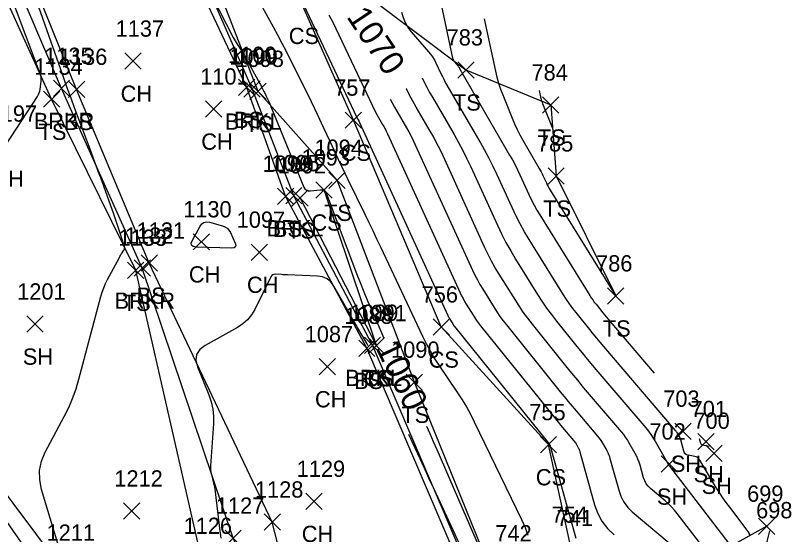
# Model space of a CAD drawing. Extents: x 1592612 to 1596497, y 111838 to 113741.
# Drawn here: x 1592792 to 1592887.3, y 113548.4 to 113612.1 of the extents above; entities that cross this region are included whole.
import ezdxf

# ---------------------------------------------------------------- set-up
doc = ezdxf.new("R2010")
doc.units = 0
for name, color, linetype in [('L_A', 7, 'Continuous'), ('L_I', 7, 'Continuous'), ('L_TIC', 7, 'Continuous'), ('LAWE', 7, 'Continuous'), ('LELB', 7, 'Continuous'), ('LSOGCMA', 7, 'Continuous'), ('LSOGCMA_T', 7, 'Continuous'), ('LSOGCMI', 7, 'Continuous')]:
    doc.layers.add(name, color=color, linetype=linetype)

msp = doc.modelspace()

# ---------------------------------------------------------------- linework, layer by layer
at = {"layer": 'L_TIC'}
for points in [[(1592805.447, 113605.527), (1592807.447, 113607.527)], [(1592807.447, 113605.527), (1592805.447, 113607.527)], [(1592846.35, 113604.446), (1592848.35, 113606.446)], [(1592848.35, 113604.446), (1592846.35, 113606.446)], [(1592796.669, 113602.177), (1592798.669, 113604.177)], [(1592798.669, 113602.177), (1592796.669, 113604.177)], [(1592819.421, 113602.303), (1592821.421, 113604.303)], [(1592821.421, 113602.303), (1592819.421, 113604.303)], [(1592820.08, 113602.103), (1592822.08, 113604.103)], [(1592822.08, 113602.103), (1592820.08, 113604.103)], [(1592798.527, 113602.061), (1592800.527, 113604.061)], [(1592800.527, 113602.061), (1592798.527, 113604.061)], [(1592820.816, 113601.808), (1592822.816, 113603.808)], [(1592822.816, 113601.808), (1592820.816, 113603.808)], [(1592795.452, 113600.853), (1592797.452, 113602.853)], [(1592797.452, 113600.853), (1592795.452, 113602.853)], [(1592815.353, 113599.643), (1592817.353, 113601.643)], [(1592817.353, 113599.643), (1592815.353, 113601.643)], [(1592856.769, 113600.143), (1592858.769, 113602.143)], [(1592858.769, 113600.143), (1592856.769, 113602.143)], [(1592832.529, 113598.277), (1592834.529, 113600.277)], [(1592834.529, 113598.277), (1592832.529, 113600.277)], [(1592830.516, 113590.894), (1592832.516, 113592.894)], [(1592832.516, 113590.894), (1592830.516, 113592.894)], [(1592857.441, 113591.421), (1592859.441, 113593.421)], [(1592859.441, 113591.421), (1592857.441, 113593.421)], [(1592828.931, 113589.704), (1592830.931, 113591.704)], [(1592830.931, 113589.704), (1592828.931, 113591.704)], [(1592824.196, 113588.927), (1592826.196, 113590.927)], [(1592826.196, 113588.927), (1592824.196, 113590.927)], [(1592825.212, 113588.998), (1592827.212, 113590.998)], [(1592827.212, 113588.998), (1592825.212, 113590.998)], [(1592825.981, 113588.728), (1592827.981, 113590.728)], [(1592827.981, 113588.728), (1592825.981, 113590.728)], [(1592813.832, 113583.335), (1592815.832, 113585.335)], [(1592815.832, 113583.335), (1592813.832, 113585.335)], [(1592820.965, 113582.057), (1592822.965, 113584.057)], [(1592822.965, 113582.057), (1592820.965, 113584.057)], [(1592807.456, 113580.722), (1592809.456, 113582.722)], [(1592809.456, 113580.722), (1592807.456, 113582.722)], [(1592805.797, 113579.845), (1592807.797, 113581.845)], [(1592807.797, 113579.845), (1592805.797, 113581.845)], [(1592806.597, 113580.108), (1592808.597, 113582.108)], [(1592808.597, 113580.108), (1592806.597, 113582.108)], [(1592864.761, 113576.691), (1592866.761, 113578.691)], [(1592866.761, 113576.691), (1592864.761, 113578.691)], [(1592793.428, 113573.235), (1592795.428, 113575.235)], [(1592795.428, 113573.235), (1592793.428, 113575.235)], [(1592843.332, 113572.876), (1592845.332, 113574.876)], [(1592845.332, 113572.876), (1592843.332, 113574.876)], [(1592834.177, 113570.255), (1592836.177, 113572.255)], [(1592836.177, 113570.255), (1592834.177, 113572.255)], [(1592834.879, 113570.623), (1592836.879, 113572.623)], [(1592836.879, 113570.623), (1592834.879, 113572.623)], [(1592835.353, 113570.585), (1592837.353, 113572.585)], [(1592837.353, 113570.585), (1592835.353, 113572.585)], [(1592835.353, 113570.585), (1592837.353, 113572.585)], [(1592837.353, 113570.585), (1592835.353, 113572.585)], [(1592829.322, 113568.002), (1592831.322, 113570.002)], [(1592831.322, 113568.002), (1592829.322, 113570.002)], [(1592840.019, 113566.093), (1592842.019, 113568.093)], [(1592842.019, 113566.093), (1592840.019, 113568.093)], [(1592873.035, 113560.076), (1592875.035, 113562.076)], [(1592875.035, 113560.076), (1592873.035, 113562.076)], [(1592856.498, 113558.424), (1592858.498, 113560.424)], [(1592858.498, 113558.424), (1592856.498, 113560.424)], [(1592875.834, 113558.804), (1592877.834, 113560.804)], [(1592877.834, 113558.804), (1592875.834, 113560.804)], [(1592876.826, 113557.367), (1592878.826, 113559.367)], [(1592878.826, 113557.367), (1592876.826, 113559.367)], [(1592871.335, 113556.042), (1592873.335, 113558.042)], [(1592873.335, 113556.042), (1592871.335, 113558.042)], [(1592827.7, 113551.46), (1592829.7, 113553.46)], [(1592829.7, 113551.46), (1592827.7, 113553.46)], [(1592805.288, 113550.276), (1592807.288, 113552.276)], [(1592807.288, 113550.276), (1592805.288, 113552.276)], [(1592822.559, 113548.918), (1592824.559, 113550.918)], [(1592824.559, 113548.918), (1592822.559, 113550.918)], [(1592883.313, 113548.407), (1592885.313, 113550.407)], [(1592885.313, 113548.407), (1592883.313, 113550.407)], [(1592817.761, 113546.936), (1592819.761, 113548.936)], [(1592819.761, 113546.936), (1592817.761, 113548.936)]]:
    msp.add_lwpolyline(points, dxfattribs=at)
at = {"layer": 'LAWE'}
for points in [[(1592886.537, 113460.922), (1592877.744, 113481.574), (1592863.095, 113501.144), (1592852.902, 113518.209), (1592848.805, 113541.382), (1592835.879, 113571.623), (1592826.212, 113589.998), (1592821.08, 113603.103), (1592811.502, 113625.047), (1592801.909, 113656.496), (1592787.746, 113677.481), (1592769.551, 113701.793), (1592752.509, 113717.946)], [(1592867.645, 113460.38), (1592859.409, 113477.515), (1592844.793, 113495.549), (1592832.37, 113516.6), (1592826.928, 113530.545), (1592818.762, 113547.936), (1592807.597, 113581.108), (1592797.669, 113603.177), (1592787.513, 113626.88), (1592776.477, 113646.362), (1592766.38, 113665.342), (1592748.736, 113682.085), (1592730.356, 113695.945)]]:
    msp.add_lwpolyline(points, dxfattribs=at)
at = {"layer": 'LELB'}
for points in [[(1592764.358, 113725.461), (1592786.757, 113707.3), (1592794.357, 113706.99), (1592806.432, 113680.654), (1592807.376, 113668.893), (1592816.061, 113658.432), (1592824.781, 113665.882), (1592828.389, 113642.22), (1592829.203, 113619.126), (1592847.35, 113605.446), (1592857.769, 113601.143), (1592858.44, 113592.421), (1592865.761, 113577.691)], [(1592886.583, 113460.952), (1592879.778, 113482.315), (1592863.966, 113501.755), (1592853.366, 113518.29), (1592851.192, 113542.037), (1592841.019, 113567.093), (1592831.516, 113591.894), (1592821.816, 113602.808), (1592813.329, 113624.79), (1592804.232, 113657.067), (1592789.644, 113678.369), (1592770.935, 113703.549), (1592752.623, 113718.428)], [(1592886.43, 113460.851), (1592879.543, 113465.926), (1592876.137, 113481.194), (1592862.304, 113500.643), (1592852.529, 113517.932), (1592848.162, 113540.894), (1592835.177, 113571.255), (1592825.196, 113589.927), (1592820.421, 113603.303), (1592810.027, 113625.391), (1592799.468, 113655.332), (1592786.607, 113676.744), (1592768.899, 113700.806), (1592752.213, 113717.027)], [(1592869.098, 113460.398), (1592860.441, 113478.115), (1592844.631, 113496.556), (1592834.165, 113516.964), (1592828.396, 113531.171), (1592823.559, 113549.918), (1592808.456, 113581.723), (1592799.527, 113603.061), (1592789.48, 113627.849), (1592777.21, 113647.427), (1592766.461, 113666.146), (1592749.422, 113683.288), (1592730.933, 113697.021)], [(1592856.492, 113476.867), (1592843.193, 113495.045), (1592831.688, 113516.664), (1592823.204, 113528.692), (1592814.853, 113545.459), (1592806.797, 113580.845), (1592796.452, 113601.854), (1592785.293, 113626.354), (1592775.723, 113645.654), (1592766.309, 113664.453), (1592745.043, 113679.184), (1592727.847, 113694.217)], [(1592701.588, 113659.774), (1592726.097, 113635.895), (1592737.453, 113625.119), (1592757.272, 113620.552), (1592765.525, 113604.487), (1592785.217, 113593.362), (1592785.143, 113579.955), (1592783.097, 113567.939), (1592785.828, 113560.008), (1592797.4, 113544.62), (1592809.213, 113533.643), (1592811.425, 113524.524), (1592820.841, 113522.69), (1592826.429, 113512.914)], [(1592860.223, 113546.827), (1592857.498, 113559.424), (1592844.332, 113573.876), (1592833.529, 113599.277), (1592827.152, 113613.626), (1592814.151, 113635.371), (1592812.219, 113639.821)], [(1592836.353, 113571.585), (1592829.931, 113590.704)], [(1592836.352, 113571.585), (1592826.981, 113589.728)], [(1592884.313, 113549.407), (1592873.166, 113543.239), (1592866.23, 113535.449), (1592862.822, 113524.774)]]:
    msp.add_lwpolyline(points, dxfattribs=at)
at = {"layer": 'LSOGCMA'}
for points in [[(1592797.873, 113545.124), (1592795.23, 113553.926), (1592794.991, 113555.102), (1592794.986, 113556.254), (1592795.216, 113557.383), (1592795.68, 113558.488), (1592798.008, 113562.865), (1592798.556, 113563.972), (1592799.04, 113565.105), (1592799.457, 113566.264), (1592799.809, 113567.449), (1592802.52, 113577.635), (1592802.679, 113578.168), (1592802.867, 113578.69), (1592803.084, 113579.2), (1592803.332, 113579.698), (1592804.783, 113582.426), (1592804.845, 113582.539), (1592804.91, 113582.65), (1592804.978, 113582.76), (1592805.049, 113582.868), (1592805.34, 113583.295), (1592805.398, 113583.404), (1592805.429, 113583.517), (1592805.431, 113583.634), (1592805.405, 113583.755), (1592804.55, 113586.397), (1592804.392, 113586.877), (1592804.23, 113587.356), (1592804.063, 113587.834), (1592803.892, 113588.31), (1592802.483, 113592.173), (1592802.19, 113592.975), (1592801.895, 113593.776), (1592801.598, 113594.577), (1592801.301, 113595.377), (1592799.281, 113600.792), (1592798.848, 113601.963), (1592798.42, 113603.135), (1592797.998, 113604.309), (1592797.582, 113605.486), (1592791.75, 113622.113)], [(1592816.191, 113614.522), (1592818.757, 113609.429), (1592818.868, 113609.217), (1592818.985, 113609.009), (1592819.109, 113608.804), (1592819.239, 113608.603), (1592819.773, 113607.807), (1592819.904, 113607.606), (1592820.031, 113607.403), (1592820.153, 113607.197), (1592820.271, 113606.988), (1592822.04, 113603.77), (1592822.106, 113603.65), (1592822.17, 113603.529), (1592822.233, 113603.408), (1592822.294, 113603.286), (1592822.539, 113602.798), (1592822.599, 113602.675), (1592822.659, 113602.552), (1592822.718, 113602.429), (1592822.775, 113602.305), (1592823.163, 113601.467), (1592823.245, 113601.285), (1592823.326, 113601.103), (1592823.405, 113600.919), (1592823.482, 113600.735), (1592827.448, 113591.066), (1592827.582, 113590.831), (1592827.762, 113590.672), (1592827.988, 113590.589), (1592828.258, 113590.582), (1592829.431, 113590.707), (1592829.701, 113590.7), (1592829.924, 113590.616), (1592830.099, 113590.455), (1592830.227, 113590.217), (1592833.928, 113580.444), (1592834.359, 113579.325), (1592834.804, 113578.212), (1592835.264, 113577.104), (1592835.736, 113576.002), (1592837.265, 113572.498)], [(1592877.265, 113545.796), (1592873.296, 113550.977), (1592872.962, 113551.389), (1592872.607, 113551.782), (1592872.232, 113552.154), (1592871.836, 113552.507), (1592870.009, 113554.048), (1592869.728, 113554.322), (1592869.496, 113554.628), (1592869.314, 113554.966), (1592869.181, 113555.336), (1592868.746, 113556.9), (1592868.63, 113557.271), (1592868.492, 113557.634), (1592868.333, 113557.988), (1592868.152, 113558.333), (1592867.384, 113559.693), (1592867.185, 113560.028), (1592866.97, 113560.352), (1592866.739, 113560.665), (1592866.493, 113560.967), (1592862.551, 113565.582), (1592861.813, 113566.452), (1592861.081, 113567.328), (1592860.356, 113568.21), (1592859.637, 113569.097), (1592855.514, 113574.222), (1592854.947, 113574.95), (1592854.403, 113575.693), (1592853.882, 113576.453), (1592853.383, 113577.23), (1592851.437, 113580.367), (1592850.963, 113581.158), (1592850.515, 113581.963), (1592850.092, 113582.782), (1592849.696, 113583.615), (1592844.539, 113594.89), (1592844.175, 113595.661), (1592843.793, 113596.423), (1592843.392, 113597.175), (1592842.972, 113597.917), (1592841.257, 113600.868), (1592840.836, 113601.61), (1592840.431, 113602.36), (1592840.043, 113603.119), (1592840.017, 113603.172)], [(1592857.986, 113598.325), (1592856.803, 113601.276), (1592856.742, 113601.436), (1592856.689, 113601.599), (1592856.642, 113601.764), (1592856.602, 113601.931), (1592856.382, 113602.938)], [(1592842.5, 113561.7), (1592842.91, 113560.795), (1592843.349, 113559.809), (1592843.782, 113558.82), (1592850.972, 113542.212)]]:
    msp.add_lwpolyline(points, dxfattribs=at)
at = {"layer": 'LSOGCMI'}
for points in [[(1592819.194, 113618.866), (1592823.667, 113610.731), (1592824.204, 113609.742), (1592824.732, 113608.749), (1592825.25, 113607.75), (1592825.758, 113606.746), (1592827.917, 113602.432), (1592828.345, 113601.569), (1592828.766, 113600.702), (1592829.18, 113599.832), (1592829.587, 113598.959), (1592831.203, 113595.46), (1592831.609, 113594.586), (1592832.02, 113593.715), (1592832.436, 113592.846), (1592832.856, 113591.979), (1592834.935, 113587.715), (1592835.421, 113586.715), (1592835.902, 113585.713), (1592836.381, 113584.71), (1592836.855, 113583.704), (1592842, 113572.746), (1592842.454, 113571.827), (1592842.942, 113570.927), (1592843.465, 113570.048), (1592844.023, 113569.188), (1592846.323, 113565.789), (1592846.882, 113564.93), (1592847.409, 113564.052), (1592847.904, 113563.156), (1592848.367, 113562.242), (1592854.208, 113550.166), (1592854.421, 113549.707), (1592854.62, 113549.241), (1592854.803, 113548.77), (1592854.97, 113548.292)], [(1592790.805, 113596.174), (1592794.712, 113602.201), (1592794.831, 113602.408), (1592794.925, 113602.624), (1592794.995, 113602.849), (1592795.041, 113603.083), (1592795.173, 113604.039), (1592795.192, 113604.276), (1592795.18, 113604.51), (1592795.14, 113604.74), (1592795.069, 113604.967), (1592792.151, 113612.707), (1592791.639, 113614.073)], [(1592844.271, 113613.691), (1592845.719, 113606.905), (1592845.756, 113606.772), (1592845.809, 113606.646), (1592845.878, 113606.529), (1592845.962, 113606.419), (1592846.408, 113605.906), (1592846.459, 113605.843), (1592846.506, 113605.778), (1592846.547, 113605.709), (1592846.584, 113605.637), (1592846.723, 113605.343), (1592846.758, 113605.271), (1592846.795, 113605.198), (1592846.834, 113605.127), (1592846.874, 113605.056), (1592852.726, 113594.99), (1592853.064, 113594.393), (1592853.386, 113593.789), (1592853.693, 113593.177), (1592853.986, 113592.557), (1592855.127, 113590.062), (1592855.421, 113589.444), (1592855.735, 113588.836), (1592856.068, 113588.238), (1592856.42, 113587.65), (1592862.561, 113577.752), (1592862.742, 113577.471), (1592862.93, 113577.196), (1592863.127, 113576.927), (1592863.333, 113576.663), (1592864.171, 113575.622), (1592864.381, 113575.362), (1592864.593, 113575.104), (1592864.808, 113574.848), (1592865.024, 113574.593), (1592870.49, 113568.194)], [(1592827.401, 113613.475), (1592833.955, 113599.597), (1592833.981, 113599.543), (1592834.008, 113599.491), (1592834.036, 113599.439), (1592834.065, 113599.387), (1592834.184, 113599.182), (1592834.214, 113599.131), (1592834.241, 113599.079), (1592834.268, 113599.026), (1592834.293, 113598.972), (1592845.117, 113575.302), (1592845.176, 113575.18), (1592845.237, 113575.06), (1592845.303, 113574.942), (1592845.372, 113574.826), (1592845.657, 113574.367), (1592845.73, 113574.254), (1592845.806, 113574.142), (1592845.886, 113574.034), (1592845.969, 113573.927), (1592857.527, 113559.559), (1592857.537, 113559.547), (1592857.547, 113559.534), (1592857.557, 113559.522), (1592857.568, 113559.51), (1592857.622, 113559.446), (1592857.626, 113559.442), (1592857.629, 113559.437), (1592857.632, 113559.433), (1592857.635, 113559.428), (1592857.646, 113559.409), (1592857.648, 113559.404), (1592857.65, 113559.4), (1592857.652, 113559.395), (1592857.654, 113559.389), (1592860.846, 113547.933)], [(1592830.503, 113612.205), (1592830.771, 113611.761), (1592831.01, 113611.298), (1592835.86, 113601.026), (1592836.002, 113600.735), (1592836.149, 113600.447), (1592836.303, 113600.162), (1592836.462, 113599.881), (1592837.114, 113598.761), (1592837.273, 113598.479), (1592837.425, 113598.193), (1592837.57, 113597.904), (1592837.709, 113597.612), (1592846.644, 113578.073), (1592846.815, 113577.714), (1592846.997, 113577.361), (1592847.19, 113577.014), (1592847.394, 113576.673), (1592848.233, 113575.321), (1592848.447, 113574.987), (1592848.672, 113574.659), (1592848.906, 113574.339), (1592849.151, 113574.026), (1592858.231, 113562.738), (1592858.477, 113562.434), (1592858.725, 113562.132), (1592858.976, 113561.832), (1592859.229, 113561.534), (1592860.579, 113559.953), (1592860.664, 113559.849), (1592860.743, 113559.742), (1592860.816, 113559.631), (1592860.885, 113559.517), (1592861.148, 113559.05), (1592861.21, 113558.932), (1592861.264, 113558.811), (1592861.311, 113558.687), (1592861.351, 113558.559), (1592863.164, 113552.051), (1592863.545, 113550.987), (1592864.069, 113550.014), (1592864.736, 113549.133), (1592865.546, 113548.344)], [(1592882.249, 113548.304), (1592882.167, 113548.542), (1592882.028, 113548.768), (1592879.76, 113551.729), (1592879.334, 113552.302), (1592878.925, 113552.885), (1592878.532, 113553.481), (1592878.156, 113554.087), (1592876.085, 113557.538), (1592875.966, 113557.699), (1592875.822, 113557.825), (1592875.653, 113557.917), (1592875.46, 113557.973), (1592874.64, 113558.128), (1592874.453, 113558.187), (1592874.305, 113558.287), (1592874.194, 113558.427), (1592874.12, 113558.608), (1592873.737, 113560.021), (1592873.705, 113560.126), (1592873.667, 113560.228), (1592873.622, 113560.327), (1592873.571, 113560.424), (1592873.356, 113560.806), (1592873.3, 113560.9), (1592873.239, 113560.991), (1592873.174, 113561.079), (1592873.105, 113561.164), (1592864.285, 113571.489), (1592863.852, 113572), (1592863.423, 113572.513), (1592862.998, 113573.029), (1592862.577, 113573.549), (1592860.9, 113575.634), (1592860.489, 113576.161), (1592860.095, 113576.7), (1592859.717, 113577.251), (1592859.356, 113577.813), (1592855.135, 113584.616), (1592854.56, 113585.577), (1592854.015, 113586.555), (1592853.502, 113587.551), (1592853.02, 113588.562), (1592851.153, 113592.643), (1592850.675, 113593.657), (1592850.172, 113594.658), (1592849.644, 113595.647), (1592849.093, 113596.623), (1592845.054, 113603.569), (1592844.861, 113603.909), (1592844.676, 113604.253), (1592844.498, 113604.601), (1592844.327, 113604.953), (1592843.659, 113606.368), (1592843.48, 113606.715), (1592843.28, 113607.046), (1592843.056, 113607.364), (1592842.811, 113607.666), (1592840.659, 113610.139), (1592840.252, 113610.668), (1592839.922, 113611.236), (1592839.667, 113611.841), (1592839.488, 113612.484)], [(1592849.583, 113611.74), (1592850.984, 113605.31), (1592851.162, 113604.565), (1592851.372, 113603.829), (1592851.611, 113603.102), (1592851.882, 113602.385), (1592853.038, 113599.502), (1592853.329, 113598.812), (1592853.645, 113598.134), (1592853.985, 113597.468), (1592854.35, 113596.814), (1592856.36, 113593.357), (1592856.483, 113593.139), (1592856.6, 113592.919), (1592856.712, 113592.696), (1592856.819, 113592.471), (1592857.234, 113591.562), (1592857.341, 113591.337), (1592857.456, 113591.116), (1592857.577, 113590.898), (1592857.705, 113590.684), (1592865.739, 113577.735)], [(1592841.973, 113604.476), (1592842.237, 113603.932), (1592842.556, 113603.308), (1592842.889, 113602.691), (1592843.235, 113602.082), (1592845.901, 113597.496), (1592846.451, 113596.523), (1592846.977, 113595.538), (1592847.478, 113594.54), (1592847.955, 113593.53), (1592851.222, 113586.385), (1592851.731, 113585.316), (1592852.274, 113584.264), (1592852.85, 113583.23), (1592853.458, 113582.214), (1592856.151, 113577.874), (1592856.692, 113577.03), (1592857.259, 113576.204), (1592857.851, 113575.395), (1592858.467, 113574.605), (1592860.984, 113571.476), (1592861.616, 113570.697), (1592862.253, 113569.922), (1592862.897, 113569.151), (1592863.546, 113568.386), (1592869.45, 113561.475), (1592869.777, 113561.073), (1592870.083, 113560.657), (1592870.369, 113560.226), (1592870.634, 113559.782), (1592872.147, 113557.101), (1592872.155, 113557.085), (1592872.162, 113557.069), (1592872.169, 113557.052), (1592872.174, 113557.035), (1592872.193, 113556.966), (1592872.199, 113556.949), (1592872.207, 113556.934), (1592872.218, 113556.92), (1592872.23, 113556.908), (1592872.312, 113556.839), (1592872.33, 113556.823), (1592872.347, 113556.807), (1592872.363, 113556.789), (1592872.378, 113556.771), (1592879.646, 113547.282)], [(1592838.054, 113601.865), (1592838.29, 113601.404), (1592838.569, 113600.886), (1592838.86, 113600.374), (1592840.043, 113598.339), (1592840.332, 113597.827), (1592840.609, 113597.308), (1592840.873, 113596.783), (1592841.124, 113596.251), (1592848.17, 113580.844), (1592848.453, 113580.248), (1592848.756, 113579.662), (1592849.076, 113579.086), (1592849.415, 113578.52), (1592850.808, 113576.275), (1592851.164, 113575.72), (1592851.537, 113575.176), (1592851.927, 113574.644), (1592852.332, 113574.124), (1592858.934, 113565.917), (1592859.416, 113565.322), (1592859.903, 113564.73), (1592860.395, 113564.142), (1592860.89, 113563.558), (1592863.536, 113560.46), (1592863.701, 113560.257), (1592863.856, 113560.047), (1592864.001, 113559.83), (1592864.135, 113559.605), (1592864.65, 113558.691), (1592864.771, 113558.46), (1592864.878, 113558.223), (1592864.971, 113557.979), (1592865.048, 113557.73), (1592866.169, 113553.707), (1592866.428, 113552.983), (1592866.784, 113552.322), (1592867.237, 113551.723), (1592867.788, 113551.187), (1592872.321, 113547.364)], [(1592835.328, 113571.566), (1592835.207, 113571.792), (1592834.979, 113572.195), (1592834.047, 113573.793), (1592833.814, 113574.193), (1592833.583, 113574.594), (1592833.353, 113574.995), (1592833.124, 113575.397), (1592831.128, 113578.905), (1592830.752, 113579.421), (1592830.291, 113579.797), (1592829.745, 113580.033), (1592829.113, 113580.129), (1592825.446, 113580.27), (1592825.258, 113580.277), (1592825.069, 113580.286), (1592824.881, 113580.295), (1592824.693, 113580.306), (1592823.939, 113580.349), (1592823.764, 113580.337), (1592823.615, 113580.28), (1592823.492, 113580.179), (1592823.395, 113580.032), (1592821.419, 113576.04), (1592821.018, 113575.36), (1592820.531, 113574.762), (1592819.957, 113574.246), (1592819.297, 113573.813), (1592815.311, 113571.592), (1592814.647, 113571.09), (1592814.271, 113570.487), (1592814.182, 113569.781), (1592814.382, 113568.972), (1592815.758, 113565.535), (1592816.052, 113564.668), (1592816.244, 113563.785), (1592816.335, 113562.885), (1592816.324, 113561.97), (1592815.986, 113556.835), (1592815.979, 113556.564), (1592815.993, 113556.294), (1592816.029, 113556.027), (1592816.086, 113555.761), (1592816.357, 113554.704), (1592816.421, 113554.438), (1592816.475, 113554.171), (1592816.521, 113553.903), (1592816.557, 113553.632), (1592817.121, 113548.815), (1592817.252, 113547.929)], [(1592847.559, 113545.109), (1592844.5, 113551.673), (1592843.935, 113552.887), (1592843.372, 113554.102), (1592842.812, 113555.319), (1592842.253, 113556.536), (1592840.359, 113560.669)], [(1592876.014, 113560.177), (1592876.167, 113559.614), (1592876.201, 113559.529), (1592876.253, 113559.464), (1592876.322, 113559.417), (1592876.409, 113559.39), (1592877.227, 113559.235)], [(1592792.727, 113547.43), (1592785.78, 113557.351)], [(1592884.629, 113548.822), (1592884.249, 113547.215)]]:
    msp.add_lwpolyline(points, dxfattribs=at)
msp.add_lwpolyline([(1592813.854, 113583.747), (1592813.65, 113583.906), (1592813.615, 113584.163), (1592813.751, 113584.518), (1592814.696, 113586.244), (1592814.909, 113586.534), (1592815.17, 113586.711), (1592815.479, 113586.776), (1592815.836, 113586.729), (1592817.435, 113586.295), (1592817.753, 113586.174), (1592818.023, 113585.995), (1592818.245, 113585.758), (1592818.418, 113585.465), (1592819.014, 113584.177), (1592819.101, 113583.896), (1592819.061, 113583.699), (1592818.895, 113583.585), (1592818.603, 113583.554), (1592814.228, 113583.684)], close=True, dxfattribs=at)

# ---------------------------------------------------------------- texts
at = {"layer": 'L_A'}
for s, p in [('CS', (1592825.593, 113608.626)), ('CH', (1592804.935, 113601.527)), ('TS', (1592845.759, 113600.446)), ('BS', (1592818.862, 113598.303)), ('BRKR', (1592794.259, 113598.177)), ('BS', (1592797.967, 113598.061)), ('BRKL', (1592817.726, 113598.103)), ('TS', (1592820.225, 113597.808)), ('TS', (1592794.862, 113596.853)), ('CH', (1592814.841, 113595.643)), ('TS', (1592856.178, 113596.143)), ('CS', (1592831.97, 113594.277)), ('SH', (1592789.336, 113591.088)), ('TS', (1592829.925, 113586.894)), ('TS', (1592856.85, 113587.421)), ('BRKL', (1592822.858, 113584.998)), ('BS', (1592823.637, 113584.927)), ('CS', (1592828.372, 113585.704)), ('TS', (1592825.391, 113584.728)), ('CH', (1592813.32, 113579.335)), ('CH', (1592820.453, 113578.057)), ('BS', (1592806.897, 113576.722)), ('BRKR', (1592804.188, 113576.108)), ('TS', (1592805.206, 113575.845)), ('TS', (1592864.171, 113572.691)), ('SH', (1592792.916, 113569.235)), ('CS', (1592842.773, 113568.876)), ('BRKL', (1592832.525, 113566.623)), ('BS', (1592833.618, 113566.255)), ('TS', (1592834.762, 113566.585)), ('CS', (1592834.793, 113566.585)), ('CH', (1592828.81, 113564.002)), ('TS', (1592839.428, 113562.093)), ('SH', (1592872.523, 113556.076)), ('CS', (1592855.938, 113554.424)), ('SH', (1592875.322, 113554.804)), ('SH', (1592876.315, 113553.367)), ('SH', (1592870.823, 113552.042)), ('CH', (1592827.188, 113547.46))]:
    msp.add_text(s, height=2, dxfattribs=at).set_placement(p)
at = {"layer": 'L_I'}
for s, p in [('1137', (1592804.321, 113609.527)), ('783', (1592844.987, 113608.446)), ('1135', (1592795.543, 113606.177)), ('1136', (1592797.345, 113606.061)), ('1100', (1592818.13, 113606.303)), ('1099', (1592818.301, 113606.103)), ('1098', (1592819.044, 113605.808)), ('1134', (1592794.326, 113604.853)), ('784', (1592855.407, 113604.143)), ('1101', (1592814.715, 113603.643)), ('757', (1592831.167, 113602.277)), ('1197', (1592788.722, 113599.088)), ('785', (1592856.078, 113595.421)), ('1094', (1592828.744, 113594.894)), ('1093', (1592827.16, 113593.704)), ('1096', (1592822.369, 113592.927)), ('1095', (1592823.441, 113592.998)), ('1092', (1592824.21, 113592.728)), ('1130', (1592812.619, 113587.335)), ('1097', (1592819.194, 113586.057)), ('1132', (1592805.471, 113584.108)), ('1131', (1592806.897, 113584.722)), ('1133', (1592804.671, 113583.845)), ('786', (1592863.344, 113580.691)), ('1201', (1592792.223, 113577.235)), ('756', (1592841.915, 113576.876)), ('1089', (1592833.1, 113574.623)), ('1091', (1592834.148, 113574.585)), ('1091', (1592834.148, 113574.585)), ('1088', (1592832.406, 113574.255)), ('1087', (1592827.55, 113572.002)), ('1090', (1592838.16, 113570.093)), ('703', (1592871.594, 113564.076)), ('755', (1592855.135, 113562.424)), ('701', (1592874.96, 113562.804)), ('700', (1592875.299, 113561.367)), ('702', (1592869.894, 113560.042)), ('1129', (1592826.566, 113555.46)), ('1212', (1592804.162, 113554.276)), ('1128', (1592821.433, 113552.918)), ('699', (1592881.896, 113552.407)), ('1127', (1592816.636, 113550.936)), ('754', (1592857.86, 113549.827)), ('698', (1592883.002, 113550.376)), ('741', (1592858.501, 113549.413)), ('1126', (1592812.672, 113548.459)), ('1211', (1592795.841, 113547.62)), ('742', (1592850.969, 113547.545))]:
    msp.add_text(s, height=2, dxfattribs=at).set_placement(p)
at = {"layer": 'LSOGCMA_T'}
for s, rotation, p in [('1070', 303.67341, (1592832.611, 113611.976)), ('1060', 295.70853, (1592836.21, 113571.361))]:
    msp.add_text(s, height=3, rotation=rotation, dxfattribs=at).set_placement(p)

doc.saveas('drawing.dxf')
